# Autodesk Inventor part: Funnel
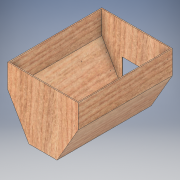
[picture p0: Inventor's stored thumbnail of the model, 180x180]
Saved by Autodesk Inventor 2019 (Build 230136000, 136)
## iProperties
Created: 2021-07
Part Number: Funnel
Material: Wood (Birch)
Document SubType Name: Modeling
Designer: Avinash
Density: 0.55 g/cm^3
Appearance: Birch - Natural Polished
Author: Avinash
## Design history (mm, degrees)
sketch "Sketch1"
  geometry: L1 (0, 0)-(30, 0); L2 (30, 0)-(75, 77.942); L3 (75, 77.942)-(75, 127.942); L4 (75, 127.942)-(0, 127.942); L5 (0, 127.942)-(0, 0)
  constraints: 10 end point, 3 perpendicular, 1 horizontal
  dimensions: "d0" = 30 distance of L1.start L1.end; "d3" = 60 deg angle of L1 L2; "d4" = 50 distance of L2.end L3.end; "d5" = 75 distance of L3.end L4.end
extrude "Extrusion1" new body sketch "Sketch1" distance "d6" = 200; taper "d7" = 0 deg
mirror "Mirror1"
shell "Shell2" dims "d9" = 2
sketch "Sketch3"
  geometry: L1 (-60, 0)-(-60, 200) reference; L2 (0, 0)-(-60, 0); L3 (-60, 0)-(-60, 80); L4 (-60, 80)-(0, 80); L5 (0, 80)-(0, 0); 1 further point
  constraints: 8 end point, 2 parallel, 1 horizontal, 1 perpendicular, 1 point on line
  dimensions: "d10" = 80 distance of L4.end L2.start
extrude "Extrusion2" cut sketch "Sketch3" distance "d11" = 2; taper "d12" = 0 deg
sketch "Sketch4"
  geometry: L1 (30, 0)-(75, 77.942) reference; L2 (30, 0)-(-30, 0); L3 (-30, 0)-(-30, 61.101); L4 (-30, 61.101)-(30, 61.101); L5 (30, 61.101)-(30, 0); 1 further point
  constraints: 8 end point, 2 parallel, 1 horizontal, 1 perpendicular
  dimensions: "d13" = 60 distance of L3.end L4.end
extrude "Extrusion3" cut sketch "Sketch4" distance "d14" = 10; taper "d15" = 0 deg
body "Solid1"
